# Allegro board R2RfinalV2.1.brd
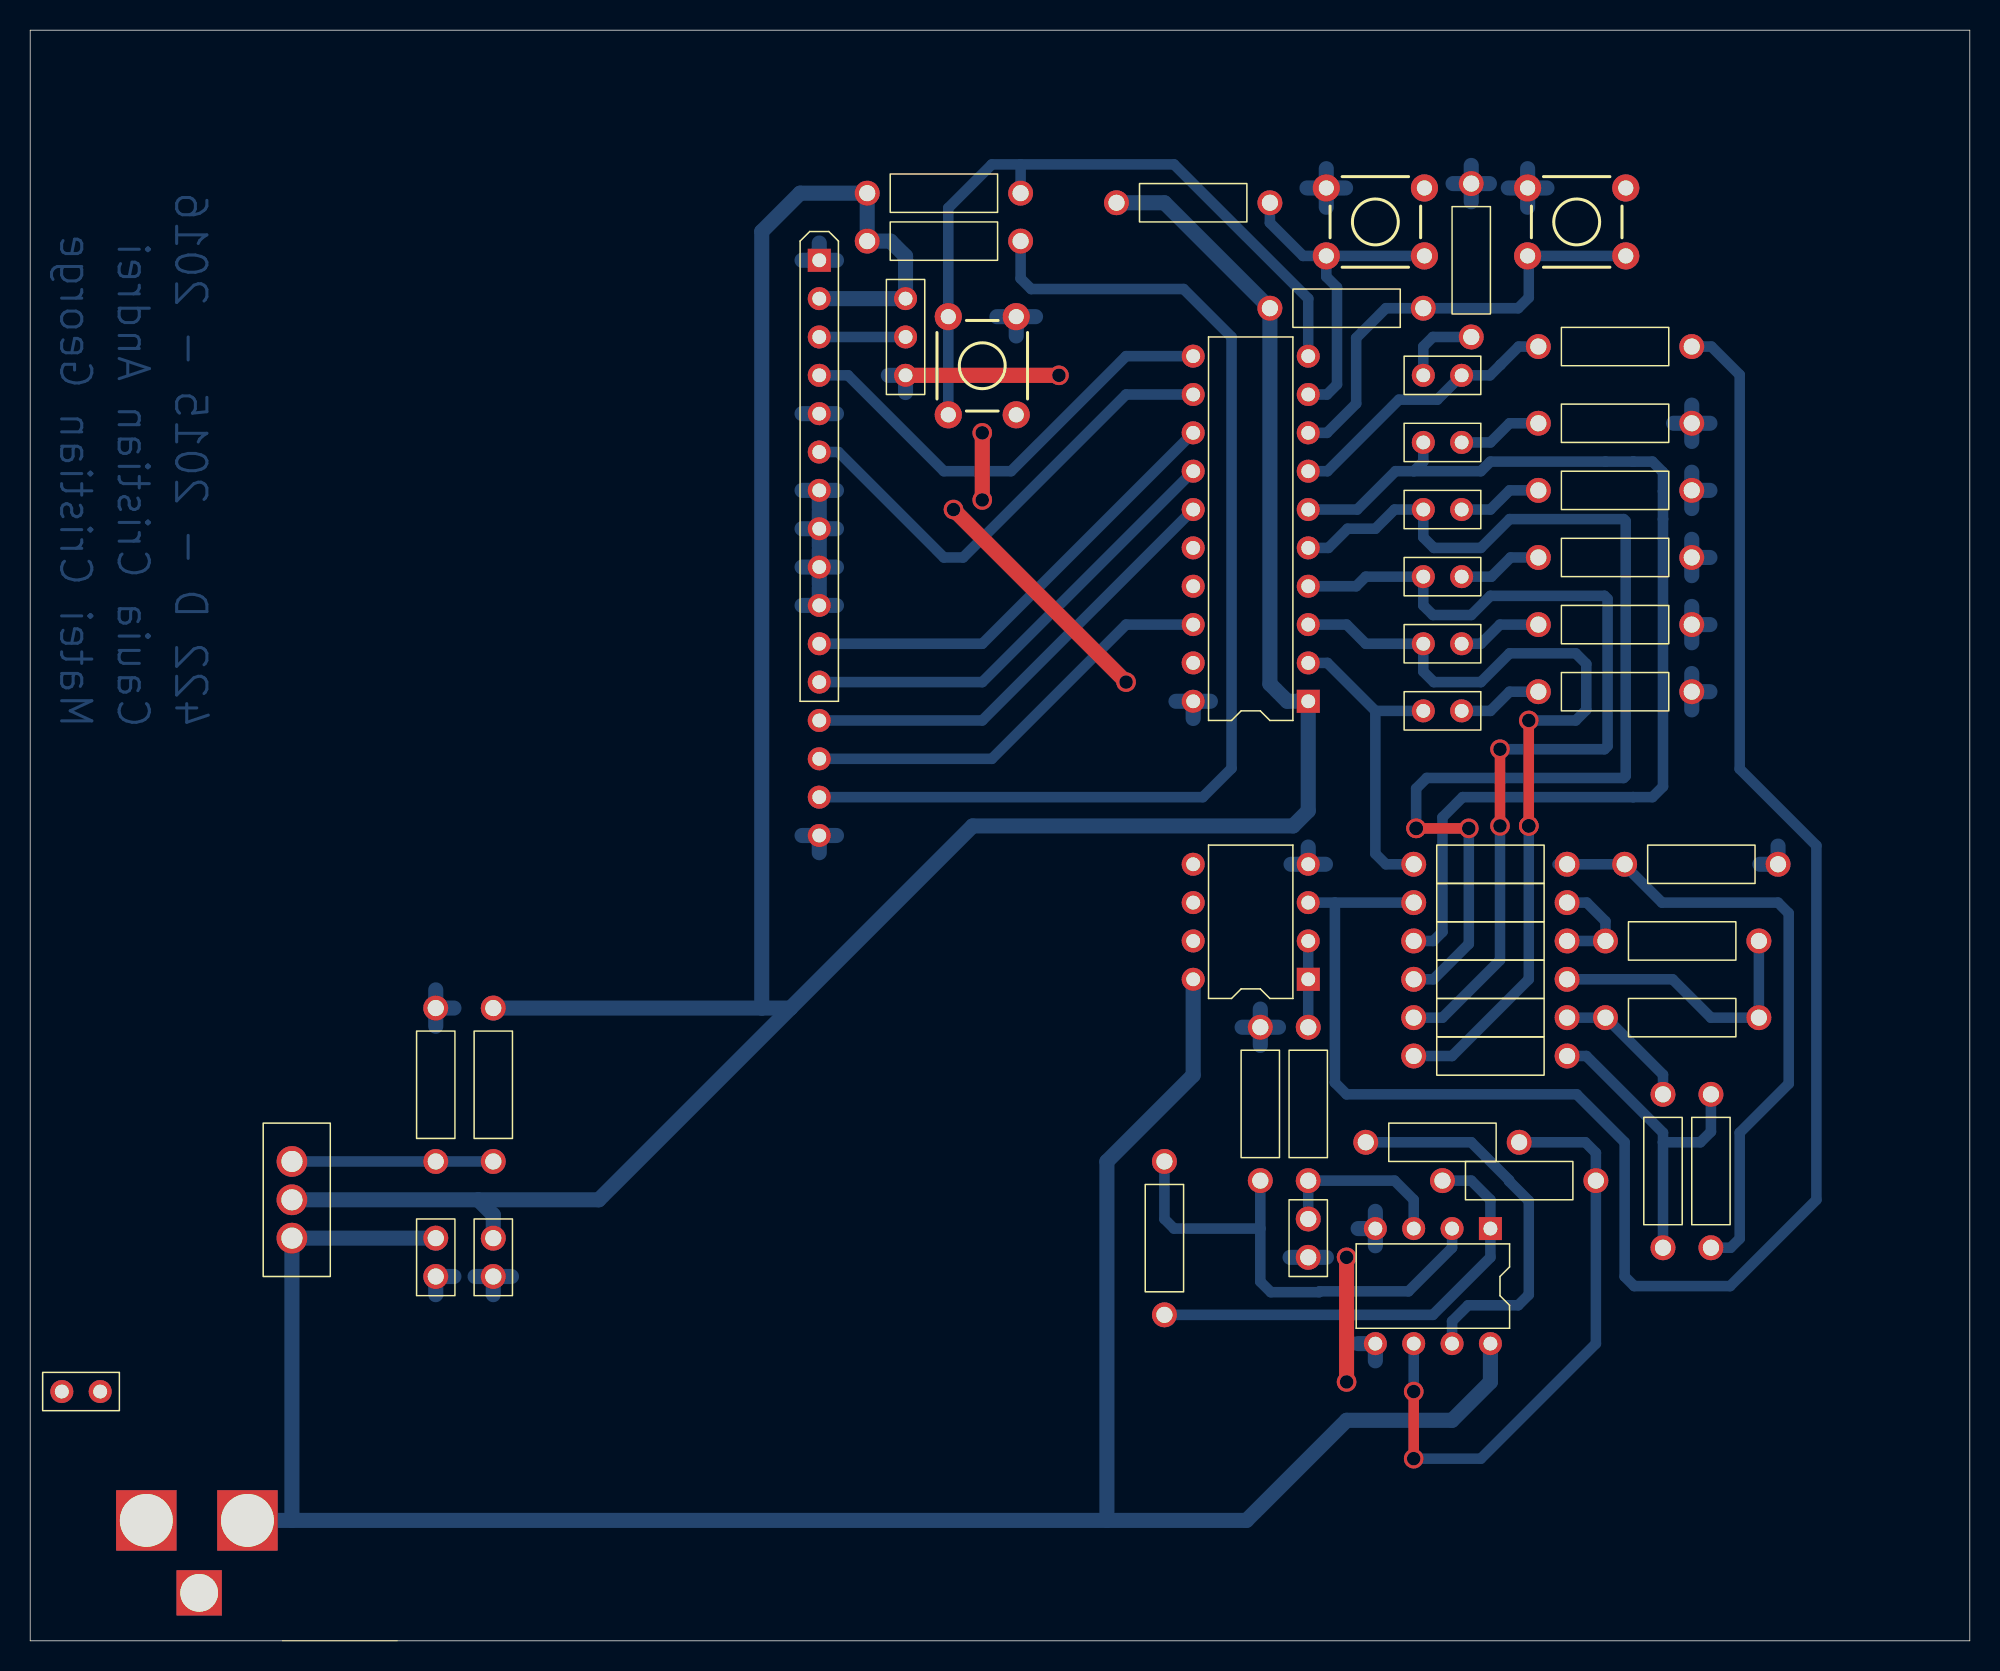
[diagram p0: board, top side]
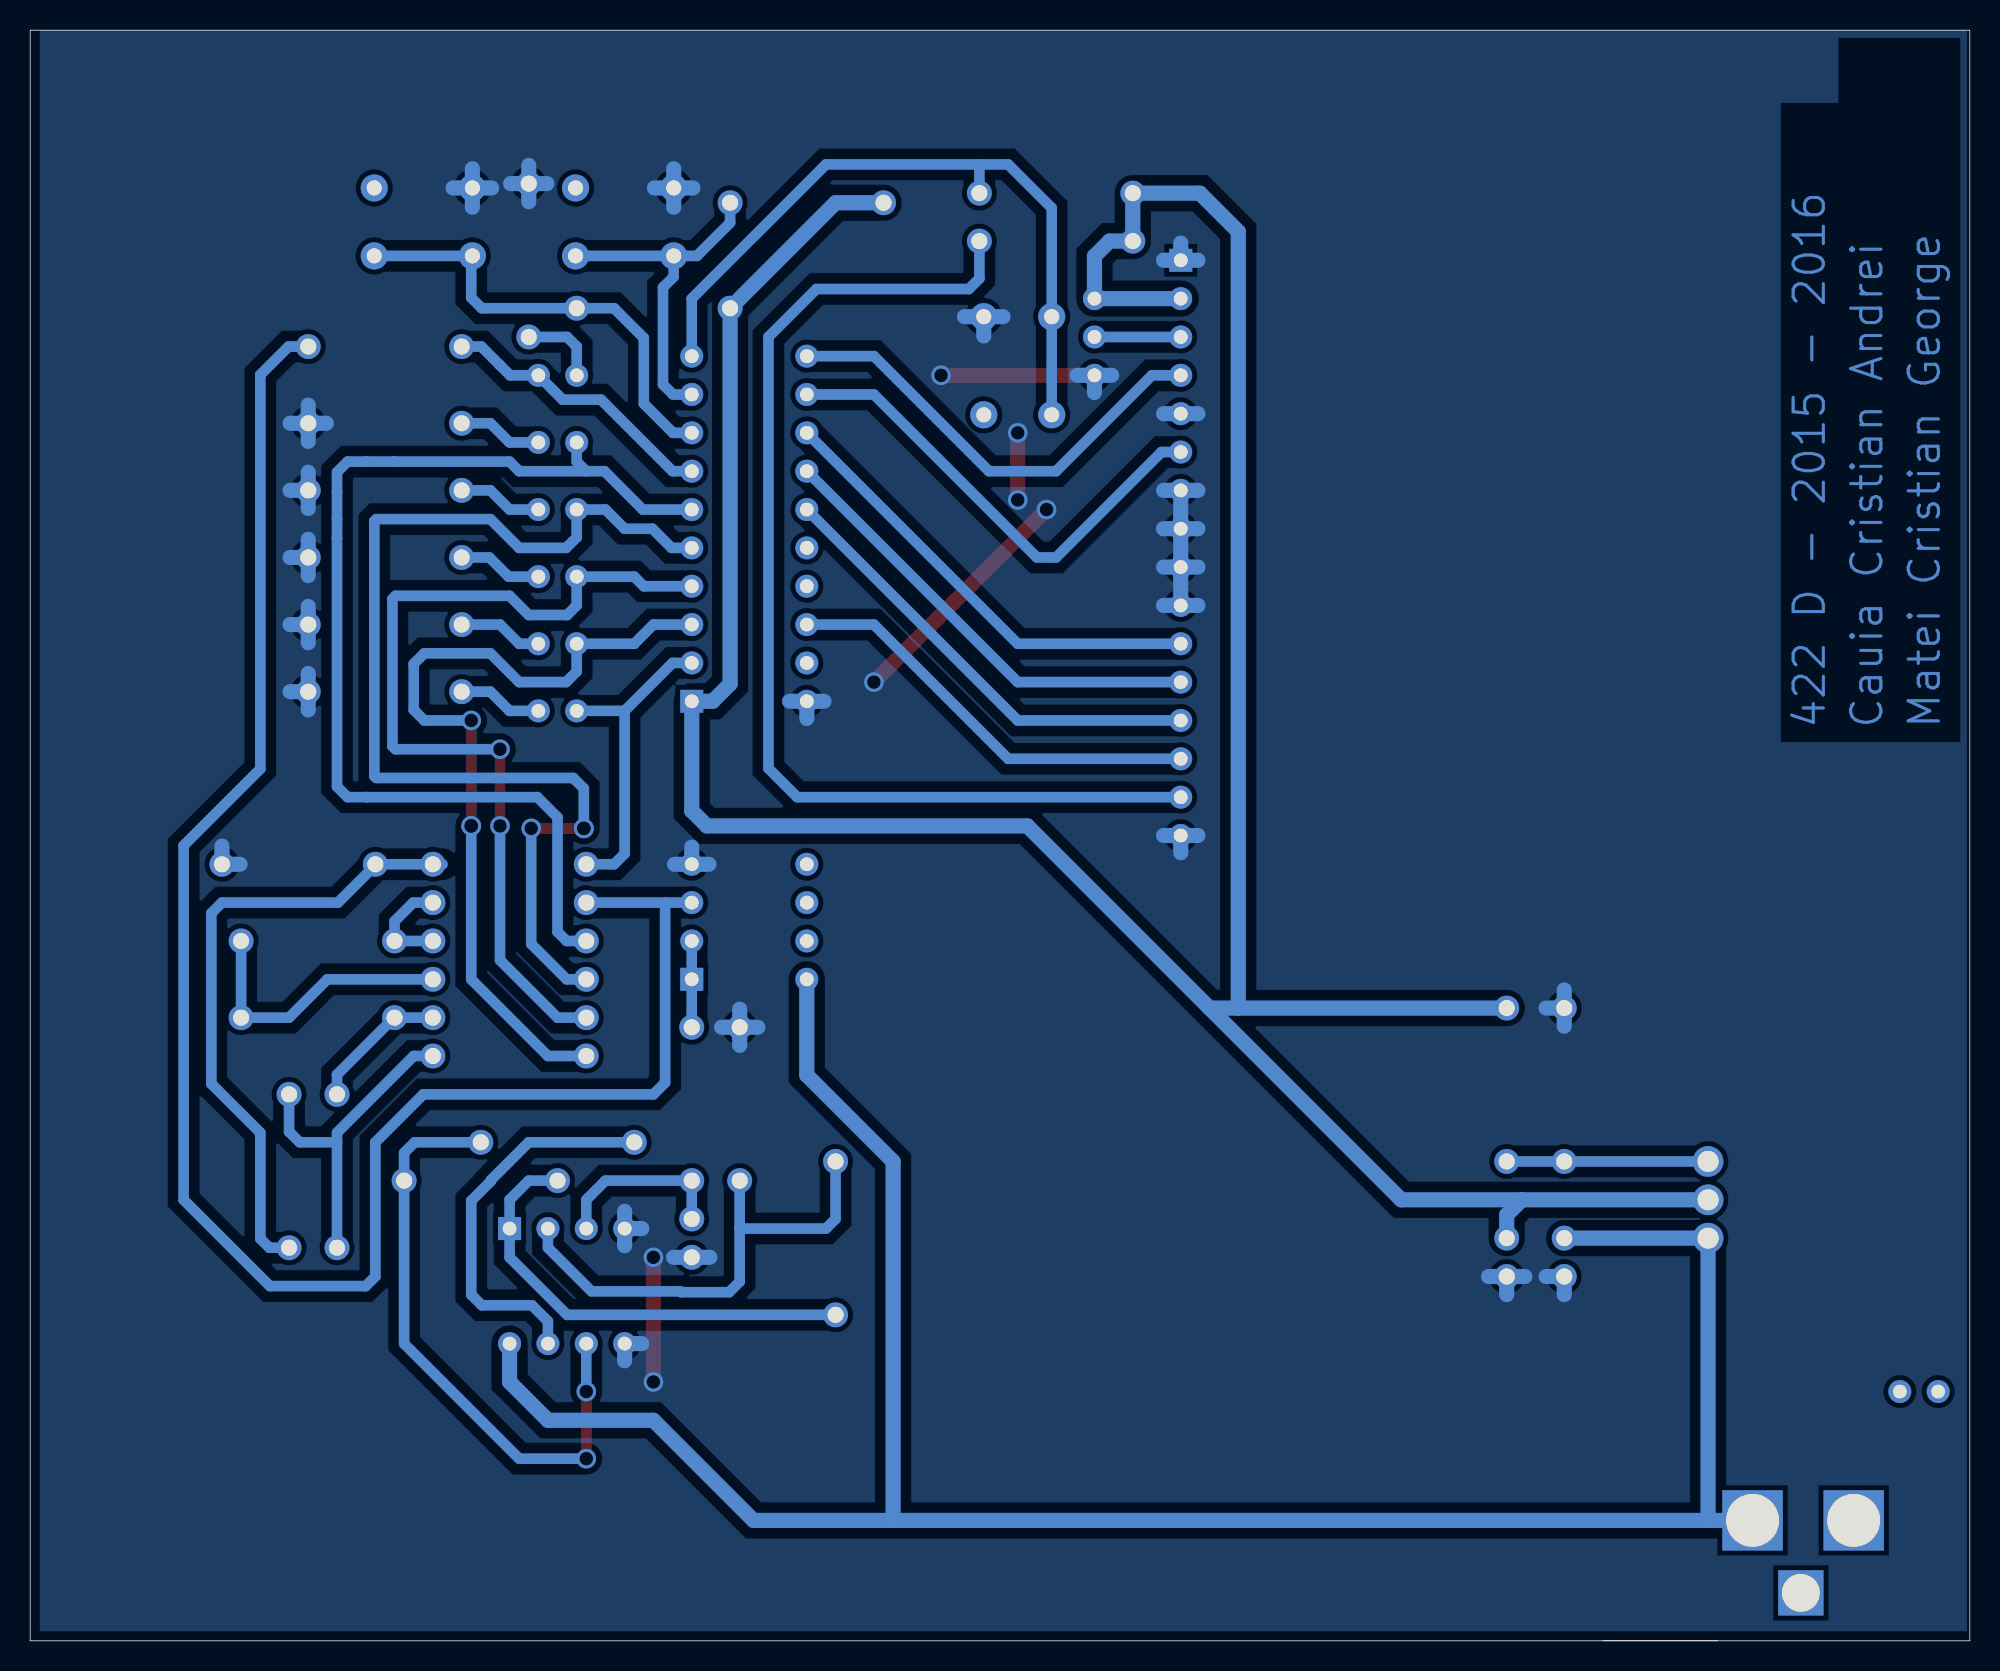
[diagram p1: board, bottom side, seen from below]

Outline 128.46 x 106.68 mm; copper layers: TOP, BOTTOM. Coordinates in mm from the lower left corner of the outline.
Outline path: 24.32,0 0,0 0,106.68 128.46,106.68 128.46,0 16.7,0

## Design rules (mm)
net group VCC: nets N20855 N35721 SW1 SW2 SW3 VCC
nets with their own width: min track width 0.7; nets N00328 N00336 N00340 N00355 N00395 N00470 N01662 N01669 N01683 N01690 N01717 N006340 N006500 N006660 N006820 N006980 N007140 N23488 N23661 N24189 N24193 N25824 N25853 N29134 N35057 N35516 N35592 N35638 N35656 N35674 N35692
nets with their own width: min track width 1; nets 0 9V

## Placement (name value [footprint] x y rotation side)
C3  10nf  [CAPCK05]  84.64 27.94 180 top
C4  10u  [CAPCK05]  26.86 24.13 0 top
C5  10u  [CAPCK05]  30.67 24.13 0 top
D1  MLED81  [JUMPER2]  94.81 83.82 180 top
D2  MLED81  [JUMPER2]  92.26 79.38 0 top
D3  MLED81  [JUMPER2]  92.26 74.93 0 top
D4  MLED81  [JUMPER2]  92.26 70.49 0 top
D5  MLED81  [JUMPER2]  92.26 66.04 0 top
D6  MLED81  [JUMPER2]  92.26 61.6 0 top
J1  Speaker  [JUMPER2]  2.09 16.51 0 top
J2  LCD 1602  [SIP16]  52.26 91.44 0 top
J3  CON3  [JACK_DC2]  0.19 3.18 0 top
R2  1k  [RES400]  101.79 48.9 90 top
R3  1k  [RES400]  114.49 46.36 90 top
R4  1k  [RES400]  104.33 41.28 270 top
R5  1k  [RES400]  108.14 26.04 0 top
R6  1k  [RES400]  111.31 26.04 0 top
R7  2k  [RES400]  91.63 51.44 270 top
R8  2k  [RES400]  91.63 38.74 270 top
R9  2k  [RES400]  91.63 41.28 270 top
R10  2k  [RES400]  91.63 43.81 270 top
R11  2k  [RES400]  91.63 46.36 270 top
R12  2k  [RES400]  99.88 85.73 270 top
R13  2k  [RES400]  115.76 51.44 90 top
R14  470  [RES400]  110.05 62.87 90 top
R15  470  [RES400]  110.05 67.31 90 top
R16  470  [RES400]  110.05 71.75 90 top
R17  470  [RES400]  110.05 76.2 90 top
R18  470  [RES400]  110.05 80.65 90 top
R19  470  [RES400]  95.44 96.52 180 top
R20  10k  [RES400]  81.47 30.48 0 top
R22  10k  [RES400]  103.69 30.48 90 top
R23  1k  [RES400]  26.86 41.91 180 top
R24  470  [RES400]  30.67 31.75 0 top
R26  33k  [RES400]  84.64 40.64 180 top
R27  10k  [RES400]  75.12 21.59 0 top
R28  10k  [RES400]  88.45 33.02 270 top
R29  1k  [JUMPER3]  57.98 83.82 90 top
R30  10k  [RES400]  65.6 95.88 90 top
R33  1k  [RES400]  55.44 92.71 270 top
R34  10k  [RES400]  82.11 95.25 90 top
R35  10k  [RES400]  92.26 88.27 90 top
SW7  SW_TC_SPST  [SW_SCHURTER_13019306L]  63.06 84.46 0 top
SW8  SW_TC_SPST  [SW_SCHURTER_13019306L]  89.09 93.98 90 top
SW9  SW_TC_SPST  [SW_SCHURTER_13019306L]  102.43 93.98 90 top
U1  MSP430G2553  [DIP20]  84.64 62.23 180 top
U7  LM317K  [TO220AB]  17.33 31.75 90 top
U9  LM358  [DIP8_3]  96.71 27.31 270 top
U10  LM358  [DIP8_3]  84.64 43.81 180 top

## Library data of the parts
C3 = C: Tolerance: ***; User Part Number: ***; signal model: DEFAULT_CAPACITOR_10000pF_1_2
C4 C5 = C: Tolerance: ***; User Part Number: ***; signal model: DEFAULT_CAPACITOR_1e+07pF_1_2
D1-D6 = MLED81: User Part Number: ***
J1 = CON2: User Part Number: ***
J2 = CON16: User Part Number: ***
J3 = CON3
R2-R6 R23 R33 = R: Tolerance: ***; User Part Number: ***; signal model: DEFAULT_RESISTOR_1000OHM_2_1
R7-R13 = R: Tolerance: ***; User Part Number: ***; signal model: DEFAULT_RESISTOR_2000OHM_2_1
R14-R19 R24 = R: Tolerance: ***; User Part Number: ***; signal model: DEFAULT_RESISTOR_470OHM_2_1
R20 R22 R27 R28 R30 R34 R35 = R: Tolerance: ***; User Part Number: ***; signal model: DEFAULT_RESISTOR_10000OHM_2_1
R26 = R: Tolerance: ***; User Part Number: ***; signal model: DEFAULT_RESISTOR_33000OHM_2_1
R29 = POT: User Part Number: ***
SW7-SW9 = SW_TC_SPST
U1 = MSP430G2553_4: Tolerance: ***; User Part Number: ***
U7 = LM317T_0
U9 = LM358: Tolerance: ***; User Part Number: ***
U10 = LM358_0: Tolerance: ***; User Part Number: ***

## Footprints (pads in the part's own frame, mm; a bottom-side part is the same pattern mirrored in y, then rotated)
CAPCK05
  round 1.651 hole 1.067: 1(0,0) 2(0,2.54)
DIP8_3
  rect 1.524x1.524 hole 0.914: 1(0,0)
  round 1.524 hole 0.914: 2(0,-2.54) 3(0,-5.08) 4(0,-7.62) 5(7.62,-7.62) 6(7.62,-5.08) 7(7.62,-2.54) 8(7.62,0)
DIP20
  rect 1.524x1.524 hole 0.914: 1(0,0)
  round 1.524 hole 0.914: 2(0,-2.54) 3(0,-5.08) 4(0,-7.62) 5(0,-10.16) 6(0,-12.7) 7(0,-15.24) 8(0,-17.78) 9(0,-20.32) 10(0,-22.86) 11(7.62,-22.86) 12(7.62,-20.32) 13(7.62,-17.78) 14(7.62,-15.24) 15(7.62,-12.7) 16(7.62,-10.16) 17(7.62,-7.62) 18(7.62,-5.08) 19(7.62,-2.54) 20(7.62,0)
JACK_DC2
  rect 4x4 hole 3.5: 1(14.2,4.8) 2(7.5,4.8)
  rect 3x3 hole 2.5: 3(11,0)
JUMPER2
  round 1.524 hole 0.914: 1(0,0) 2(2.54,0)
JUMPER3
  round 1.524 hole 0.914: 1(0,0) 2(2.54,0) 3(5.08,0)
RES400
  round 1.651 hole 1.067: 1(0,0) 2(0,10.16)
SIP16
  rect 1.524x1.524 hole 0.914: 1(0,0)
  round 1.524 hole 0.914: 2(0,-2.54) 3(0,-5.08) 4(0,-7.62) 5(0,-10.16) 6(0,-12.7) 7(0,-15.24) 8(0,-17.78) 9(0,-20.32) 10(0,-22.86) 11(0,-25.4) 12(0,-27.94) 13(0,-30.48) 14(0,-33.02) 15(0,-35.56) 16(0,-38.1)
SW_SCHURTER_13019306L
  round 1.8 hole 1: 1(-2.25,-3.25) 2(-2.25,3.25) 3(2.25,3.25) 4(2.25,-3.25)
TO220AB
  round 2.032 hole 1.397: 1(0,0) 2(-2.54,0) 3(-5.08,0)

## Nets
9V: C4.2 J3.1 U7.3(OUT) U9.8(V+) U10.8(V+)
VCC: C5.2 J2.2 R24.2 R29.3(2) R30.2 R33.1 R34.2 R35.2 U1.1(DVCC) U1.16(RESET) U7.2(IN)
0: C3.2 C4.1 C5.1 J2.1 J2.5 J2.7 J2.8 J2.9 J2.10 J2.16 J3.2 J3.3 R13.1 R14.1 R15.1 R16.1 R17.1 R18.1 R19.1 R20.2 R23.1 R29.1 SW7.3 SW8.3 SW9.3 U1.20(GROUND) U9.4(V-) U9.5(+) U10.4(V-)
SW1: R30.1 SW7.1 SW7.2 U1.10(P2_2)
SW2: R34.1 SW8.1 SW8.2 U1.9(P2_1)
SW3: R35.1 SW9.1 SW9.2 U1.8(P2_0/CS(B0))
N00328: R2.1 R3.2 R11.2
N00336: R4.1 R5.2 R9.2
N00340: R5.1 R6.2 R8.2
N00355: R2.2 R12.2 U10.3(+)
N00395: R3.1 R4.2 R10.2
N00470: R6.1 R7.2 R13.2
N01662: D5.1(A) R8.1 U1.3(P1_1/A1/RXD)
N01669: D4.1(A) R9.1 U1.4(P1_2/A2/TXD)
N01683: D2.1(A) R11.1 U1.6(P1_4/A4)
N01690: D1.1(A) R12.1 U1.7(P1_5/A5/SCK(B0))
N01717: D3.1(A) R10.1 U1.5(P1_3/A3/PUSH2)
N006340: D6.2(C) R14.2
N006500: D5.2(C) R15.2
N006660: D4.2(C) R16.2
N006820: D3.2(C) R17.2
N006980: D2.2(C) R18.2
N007140: D1.2(C) R19.2
N20855: R23.2 R24.1 U7.1(ADJ)
N23488: C3.1 R26.2 U9.3(+)
N23661: R26.1 U10.1(OUT) U10.2(-)
N24189: R20.1 R27.2 U9.2(-)
N24193: J1.1 R22.2 R27.1 U9.1(OUT)
N25824: R22.1 R28.2 U9.6(-)
N25853: J1.2 R28.1 U9.7(OUT)
N29134: D6.1(A) R7.1 U1.2(P1_0/A0/RED_LED)
N35057: J2.3 R29.2(T)
N35516: J2.4 U1.11(P2_3)
N35592: J2.6 U1.12(P2_4)
N35638: J2.11 U1.13(P2_5)
N35656: J2.12 U1.14(P1_6/A6/SCL/MISO(B0)/GREEN LED)
N35674: J2.13 U1.15(P1_7/A7/SDA/MOSE(B0))
N35692: J2.14 U1.18(P2_7/XOUT)
N35721: J2.15 R33.2

Pads without a net: SW7 4; SW8 4; SW9 4; U1 17 19; U10 5 6 7

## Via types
v1: diameter 1.3, hole 0.9, TOP to BOTTOM, 17 vias

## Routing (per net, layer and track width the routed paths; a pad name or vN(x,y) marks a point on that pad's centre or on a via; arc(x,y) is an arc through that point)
9V: length 155.1
  BOTTOM w1: 17.33,7.98 J3.1 ; 17.33,7.98 71.31,7.98 ; 17.33,7.98 U7.3 C4.2 ; 71.31,7.98 80.56,7.98 87.19,14.61 94.17,14.61 96.71,17.15 U9.8 ; 71.31,7.98 71.31,31.75 77.02,37.47 U10.8
VCC: length 223
  BOTTOM w1: C5.2 30.67,28.21 29.67,29.21 ; 48.45,41.91 50.36,41.91 ; 48.45,41.91 R24.2 ; 48.45,41.91 48.45,93.35 50.99,95.88 R30.2 R33.1 56.98,92.71 57.98,91.71 R29.3 J2.2 ; 50.36,41.91 37.65,29.21 29.67,29.21 ; 50.36,41.91 62.42,53.98 83.64,53.98 84.64,54.98 U1.1 83.26,62.23 82.11,63.38 R35.2 75.12,95.25 R34.2 ; 29.67,29.21 U7.2
0: length 137.6
  TOP w1: v1(61.15,74.93) v1(72.58,63.5) ; v1(87.19,25.4) v1(87.19,17.15) ; v1(68.13,83.82) R29.1 58.05,83.75 ; v1(63.06,75.56) v1(63.06,80.01)
  BOTTOM w1: 115.76,52.64 R13.1 114.56,51.44 ; R16.1 110.05,72.96 ; R16.1 111.25,71.75 ; R16.1 110.05,70.55 ; 87.95,19.69 U9.5 89.09,18.55 ; 53.4,81.28 J2.5 51.12,81.28 ; R19.1 96.64,96.52 ; R19.1 94.24,96.52 ; R19.1 95.44,95.32 ; R19.1 95.44,97.72 ; 51.12,76.2 J2.7 ; J2.7 53.4,76.2 ; J2.7 52.26,75.06 ; 52.26,72.52 J2.8 ; J2.8 52.26,74.8 ; J2.8 51.12,73.66 ; J2.8 53.4,73.66 ; 110.05,79.44 R18.1 ; R18.1 111.25,80.65 ; R18.1 110.05,81.85 ; R18.1 108.84,80.65 ; 89.09,26.17 U9.4 ; U9.4 87.95,27.31 ; U9.4 89.09,28.44 ; J2.10 52.26,69.72 ; J2.10 53.4,68.58 ; J2.10 51.12,68.58 ; 83.5,51.44 U10.4 ; U10.4 85.79,51.44 ; U10.4 84.64,52.57 ; R14.1 111.25,62.87 ; R14.1 110.05,61.66 ; R14.1 110.05,64.07 ; 51.12,91.44 J2.1 ; J2.1 52.26,92.58 ; J2.1 53.4,91.44 ; U1.20 78.17,62.23 ; U1.20 75.88,62.23 ; U1.20 77.02,61.09 ; 110.05,75 R17.1 ; R17.1 111.25,76.2 ; R17.1 110.05,77.4 ; 52.26,69.98 J2.9 ; J2.9 52.26,72.26 ; J2.9 53.4,71.12 ; J2.9 51.12,71.12 ; R15.1 110.05,68.51 ; R15.1 111.25,67.31 ; R15.1 110.05,66.11 ; 83.44,25.4 C3.2 85.85,25.4 ; SW8.3 87.12,96.23 ; SW8.3 85.84,94.95 ; SW8.3 84.56,96.23 ; SW8.3 85.84,97.51 ; 57.98,82.68 R29.1 ; R29.1 59.12,83.82 ; R29.1 56.83,83.82 ; SW9.3 99.18,97.51 ; SW9.3 97.9,96.23 ; SW9.3 99.18,94.95 ; SW9.3 100.45,96.23 ; R23.1 28.06,41.91 ; R23.1 26.86,40.71 ; R23.1 26.86,43.11 ; C5.1 31.87,24.13 ; C5.1 29.47,24.13 ; C5.1 30.67,22.93 ; 28.06,24.13 C4.1 26.86,22.93 ; 52.26,52.2 J2.16 ; J2.16 51.12,53.34 ; J2.16 53.4,53.34 ; 80.27,40.64 R20.2 ; R20.2 81.47,41.84 ; R20.2 81.47,39.44 ; R20.2 82.67,40.64 ; 65.31,86.43 SW7.3 ; SW7.3 64.03,87.71 ; SW7.3 66.58,87.71
SW1: length 48.1
  BOTTOM w0.7: 65.6,97.79 63.69,97.79 60.81,94.91 SW7.2 SW7.1 ; 65.6,97.79 75.75,97.79 84.64,88.9 U1.10 ; 65.6,97.79 R30.1
SW2: length 23.5
  BOTTOM w0.7: R34.1 82.11,93.93 84.3,91.73 SW8.2 ; SW8.2 85.84,90.35 86.55,89.64 86.55,83.22 85.88,82.55 U1.9 ; SW8.2 SW8.1
SW3: length 30.2
  BOTTOM w0.7: SW9.1 SW9.2 99.25,91.66 99.25,88.97 98.55,88.27 R35.1 89.79,88.27 87.82,86.3 87.82,81.95 85.88,80.01 U1.8
N00328: length 6.9
  BOTTOM w0.7: R2.1 103.09,48.9 104.33,47.66 R3.2 R11.2
N00336: length 9.2
  BOTTOM w0.7: R5.2 108.14,37.5 104.36,41.28 R4.1 R9.2
N00340: length 22
  BOTTOM w0.7: 108.14,33.02 110.62,33.02 111.31,33.72 R6.2 ; 108.14,33.02 108.14,33.66 103.06,38.74 R8.2 ; 108.14,33.02 R5.1
N00355: length 124.7
  BOTTOM w0.7: R2.2 86.41,48.9 ; 86.41,48.9 86.41,36.97 87.19,36.19 102.43,36.19 105.6,33.02 105.6,24.13 106.24,23.5 112.58,23.5 118.3,29.21 118.3,52.67 113.22,57.75 113.22,83.85 111.35,85.73 R12.2 ; 86.41,48.9 84.64,48.9
N00395: length 18.8
  BOTTOM w0.7: R10.2 108.77,43.81 111.31,41.28 R4.2 R3.1
N00470: length 41.8
  BOTTOM w0.7: R6.1 112.62,26.04 113.22,26.64 113.22,33.66 116.46,36.9 116.46,48.19 115.76,48.9 108.07,48.9 105.54,51.44 ; 101.15,51.44 R7.2 105.54,51.44 ; 105.54,51.44 R13.2
N01662: length 56.2
  TOP w0.7: v1(99.25,53.98) v1(99.25,60.96)
  BOTTOM w0.7: R8.1 94.17,38.74 99.25,43.81 v1(99.25,53.98) ; U1.3 87.19,67.31 88.45,66.04 D5.1 92.26,64.2 92.96,63.5 96.07,63.5 97.98,65.41 102.36,65.41 103.06,64.71 103.06,61.66 102.36,60.96 v1(99.25,60.96)
N01669: length 61.1
  TOP w0.7: v1(97.35,53.98) v1(97.35,59.06)
  BOTTOM w0.7: v1(97.35,53.98) 97.35,45.09 93.54,41.28 R9.1 ; U1.4 87.82,69.85 88.45,70.49 D4.1 92.26,68.58 92.9,67.94 95.44,67.94 96.71,69.22 104.26,69.22 104.47,69.01 104.47,59.26 104.26,59.06 v1(97.35,59.06)
N01683: length 73.3
  BOTTOM w0.7: U1.6 87.88,74.93 90.43,77.47 91.63,77.47 ; 91.63,77.47 96.07,77.47 96.71,78.11 104.33,78.11 106.17,78.1 107.44,78.1 108.14,77.4 108.14,76.14 108.14,74.3 108.14,73.03 108.14,56.58 107.44,55.88 106.17,55.88 94.87,55.88 93.54,54.55 93.54,46.96 92.93,46.36 R11.1 ; 91.63,77.47 92.26,78.11 D2.1
N01690: length 18.7
  BOTTOM w0.7: U1.7 85.92,77.47 90.65,82.21 93.19,82.21 D1.1 96.68,83.82 97.38,84.52 98.58,85.73 R12.1
N01717: length 74.5
  TOP w0.7: v1(91.79,53.81) v1(95.28,53.81)
  BOTTOM w0.7: R10.1 92.93,43.81 95.28,46.16 v1(95.28,53.81) ; U1.5 85.98,72.39 87.25,73.66 89.09,73.66 90.36,74.93 D3.1 92.26,73.09 92.96,72.39 96.07,72.39 97.98,74.3 105.54,74.3 105.67,74.16 105.67,57.29 105.54,57.15 92.49,57.15 91.79,56.45 v1(91.79,53.81)
N006340: length 5.6
  BOTTOM w0.7: D6.2 96.71,61.6 97.98,62.87 R14.2
N006500: length 5.6
  BOTTOM w0.7: D5.2 96.07,66.04 97.35,67.31 R15.2
N006660: length 5.6
  BOTTOM w0.7: R16.2 98.05,71.75 96.77,70.49 D4.2
N006820: length 5.6
  BOTTOM w0.7: R17.2 97.98,76.2 96.71,74.93 D3.2
N006980: length 5.6
  BOTTOM w0.7: D2.2 96.71,79.38 97.98,80.65 R18.2
N007140: length 5.3
  BOTTOM w0.7: R19.2 92.9,86.36 92.26,85.73 D1.2
N20855: length 13.3
  BOTTOM w0.7: R24.1 R23.2 U7.1
N23488: length 12
  BOTTOM w0.7: U9.3 91.63,29.21 90.36,30.48 R26.2 C3.1
N23661: length 5.7
  BOTTOM w0.7: U10.2 U10.1 R26.1
N24189: length 32.6
  BOTTOM w0.7: R27.2 75.12,27.94 75.75,27.31 81.47,27.31 ; 81.47,27.31 R20.1 ; 81.47,27.31 81.47,23.79 82.17,23.09 85.36,23.09 85.4,23.15 91.28,23.15 94.17,26.04 U9.2
N24193: length 30.7
  BOTTOM w0.7: 93.54,30.48 95.44,30.48 96.71,29.21 U9.1 96.71,25.4 92.9,21.59 R27.1
N25824: length 40.8
  TOP w0.7: v1(91.63,12.06) v1(91.63,16.51)
  BOTTOM w0.7: v1(91.63,12.06) 96.07,12.06 103.69,19.69 R22.1 103.69,32.32 103,33.02 R28.2 ; v1(91.63,16.51) U9.6
N25853: length 25.9
  BOTTOM w0.7: U9.7 94.17,21.16 95.23,22.23 98.55,22.23 99.25,22.93 99.25,29.15 97.95,30.45 97.95,30.51 95.44,33.02 R28.1
N29134: length 21.2
  BOTTOM w0.7: D6.1 89.09,61.6 ; 89.09,61.6 85.92,64.77 U1.2 ; 89.09,61.6 89.09,52.13 89.79,51.44 R7.1
N35057: length 5.7
  BOTTOM w0.7: J2.3 R29.2
N35516: length 30.6
  BOTTOM w0.7: J2.4 54.17,83.82 60.51,77.47 64.96,77.47 72.58,85.09 U1.11
N35592: length 32.1
  BOTTOM w0.7: U1.12 72.58,82.55 61.79,71.75 60.51,71.75 53.53,78.74 J2.6
N35638: length 30.6
  BOTTOM w0.7: J2.11 63.06,66.04 U1.13
N35656: length 30.6
  BOTTOM w0.7: U1.14 63.06,63.5 J2.12
N35674: length 30.6
  BOTTOM w0.7: J2.13 63.06,60.96 U1.15
N35692: length 28.4
  BOTTOM w0.7: U1.18 72.58,67.31 63.69,58.42 J2.14
N35721: length 74.7
  BOTTOM w0.7: J2.15 77.66,55.88 79.56,57.79 79.56,86.36 76.39,89.54 66.3,89.54 65.6,90.24 R33.2

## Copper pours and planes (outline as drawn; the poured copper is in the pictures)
0 on BOTTOM: 0.19,106.68 0.19,0.63 127.82,0.63 127.82,106.68

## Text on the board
BOTTOM: Matei Cristian George | Cauia Cristian Andrei | 422 D - 2015 - 2016
